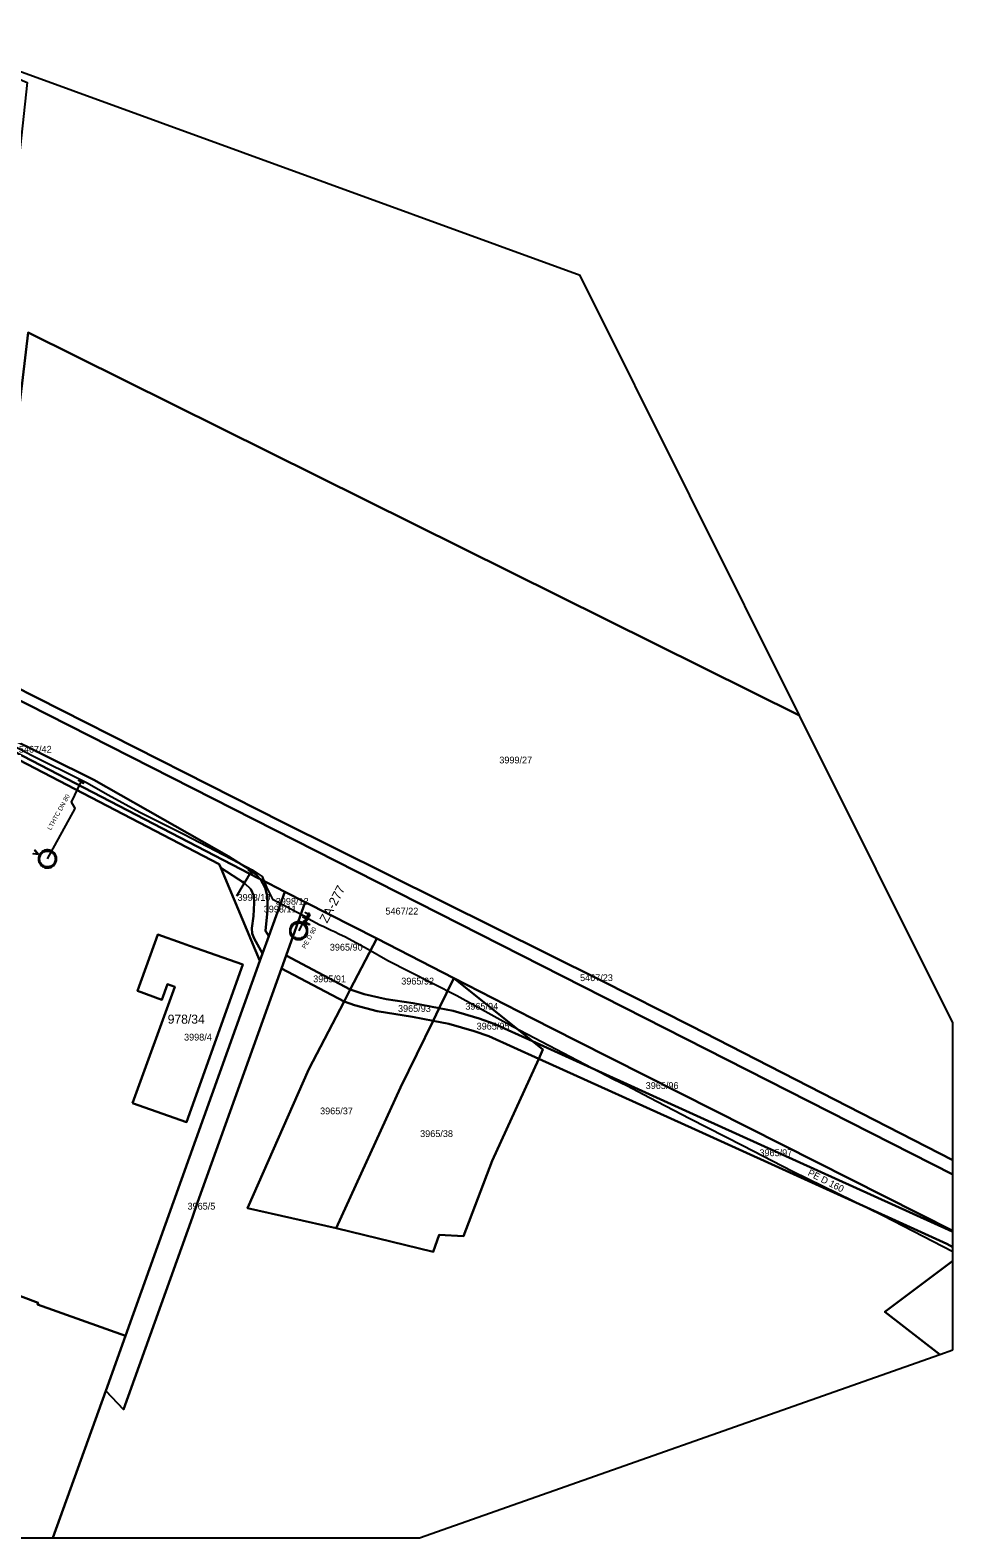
# Model space of a CAD drawing. Extents: x -570104 to -569328, y -1087857 to -1087418.
# Drawn here: x -569531.5 to -569327.7, y -1087857 to -1087524.1 of the extents above; entities that cross this region are included whole.
import ezdxf

# ---------------------------------------------------------------- set-up
doc = ezdxf.new("R2010")
doc.units = 0
for name, color, linetype in [('Adresní místo-text', 7, 'Continuous'), ('Armatura - popis', 7, 'Continuous'), ('Armatura vodovodní', 7, 'Continuous'), ('Default', 7, 'Continuous'), ('Lomový bod', 7, 'Continuous'), ('Parcela-polygon', 7, 'Continuous'), ('Parcela-text', 7, 'Continuous'), ('Přípojka vodovodní popis', 7, 'Continuous'), ('Vodovodní přípojka', 7, 'Continuous'), ('Vodovodní řad', 7, 'Continuous'), ('Vodovodní šachta', 7, 'Continuous'), ('Změna materiálu', 7, 'Continuous'), ('Řad vodovodní popis', 7, 'Continuous')]:
    doc.layers.add(name, color=color, linetype=linetype)

msp = doc.modelspace()

# ---------------------------------------------------------------- linework, layer by layer
at = {"layer": 'Armatura vodovodní'}
for points in [[(-569520.82, -1087689.73), (-569519.73, -1087690.35), (-569519.77, -1087690.41), (-569520.86, -1087689.79), (-569520.82, -1087689.73)], [(-569482.26, -1087710.27), (-569483.29, -1087709.56), (-569483.24, -1087709.49), (-569482.21, -1087710.2), (-569482.26, -1087710.27)], [(-569470.18, -1087720.56), (-569471.27, -1087719.95), (-569471.23, -1087719.89), (-569470.14, -1087720.49), (-569470.18, -1087720.56)], [(-569469.8, -1087719.13), (-569470.97, -1087721.34), (-569471.1, -1087721.27), (-569469.94, -1087719.06), (-569469.8, -1087719.13)]]:
    msp.add_lwpolyline(points, dxfattribs=at)
at = {"layer": 'Default'}
for points in [[(-569530.04, -1087705.98), (-569529.94, -1087705.99), (-569529.87, -1087706.01), (-569529.93, -1087705.95), (-569529.99, -1087705.88)], [(-569529.48, -1087706.22), (-569529.25, -1087705.78), (-569528.81, -1087705.47), (-569528.38, -1087705.16), (-569527.83, -1087705.13), (-569527.28, -1087705.11), (-569526.82, -1087705.34), (-569526.36, -1087705.57), (-569526.06, -1087706.01), (-569525.75, -1087706.46), (-569525.73, -1087707), (-569525.71, -1087707.54), (-569525.94, -1087708), (-569526.17, -1087708.45), (-569526.61, -1087708.76), (-569527.06, -1087709.06), (-569527.6, -1087709.08), (-569528.13, -1087709.11), (-569528.59, -1087708.88), (-569529.06, -1087708.64), (-569529.36, -1087708.19), (-569529.67, -1087707.74), (-569529.69, -1087707.21), (-569529.7, -1087706.67), (-569529.48, -1087706.22)], [(-569529.26, -1087706.33), (-569529.45, -1087706.72), (-569529.44, -1087707.19), (-569529.43, -1087707.66), (-569529.16, -1087708.06), (-569528.89, -1087708.45), (-569528.48, -1087708.66), (-569528.08, -1087708.86), (-569527.61, -1087708.84), (-569527.14, -1087708.82), (-569526.75, -1087708.55), (-569526.36, -1087708.29), (-569526.16, -1087707.89), (-569525.96, -1087707.48), (-569525.98, -1087707.01), (-569526, -1087706.54), (-569526.26, -1087706.15), (-569526.53, -1087705.76), (-569526.93, -1087705.56), (-569527.33, -1087705.36), (-569527.81, -1087705.38), (-569528.29, -1087705.4), (-569528.68, -1087705.67), (-569529.06, -1087705.94), (-569529.26, -1087706.33)], [(-569484.57, -1087712.21), (-569484.58, -1087712.21), (-569484.58, -1087712.2), (-569484.59, -1087712.19), (-569484.59, -1087712.18), (-569484.59, -1087712.17), (-569484.58, -1087712.16), (-569484.58, -1087712.15), (-569484.57, -1087712.15)], [(-569484.53, -1087712.15), (-569484.52, -1087712.15), (-569484.52, -1087712.16), (-569484.51, -1087712.17), (-569484.51, -1087712.18), (-569484.51, -1087712.19), (-569484.52, -1087712.2), (-569484.52, -1087712.21), (-569484.53, -1087712.21)], [(-569472.22, -1087720.97), (-569471.72, -1087720.97), (-569471.25, -1087721.22), (-569470.78, -1087721.48), (-569470.51, -1087721.95), (-569470.24, -1087722.43), (-569470.24, -1087722.95), (-569470.24, -1087723.46), (-569470.5, -1087723.93), (-569470.76, -1087724.4), (-569471.24, -1087724.66), (-569471.71, -1087724.93), (-569472.22, -1087724.93), (-569472.73, -1087724.93), (-569473.2, -1087724.66), (-569473.68, -1087724.4), (-569473.94, -1087723.93), (-569474.2, -1087723.46), (-569474.2, -1087722.95), (-569474.2, -1087722.43), (-569473.93, -1087721.95), (-569473.67, -1087721.48), (-569473.2, -1087721.22), (-569472.72, -1087720.97), (-569472.22, -1087720.97)], [(-569472.22, -1087721.21), (-569472.66, -1087721.21), (-569473.07, -1087721.44), (-569473.49, -1087721.66), (-569473.72, -1087722.08), (-569473.95, -1087722.5), (-569473.95, -1087722.95), (-569473.95, -1087723.4), (-569473.72, -1087723.81), (-569473.49, -1087724.22), (-569473.08, -1087724.45), (-569472.67, -1087724.68), (-569472.22, -1087724.68), (-569471.77, -1087724.68), (-569471.36, -1087724.45), (-569470.94, -1087724.22), (-569470.72, -1087723.81), (-569470.49, -1087723.4), (-569470.49, -1087722.95), (-569470.49, -1087722.5), (-569470.72, -1087722.08), (-569470.96, -1087721.66), (-569471.37, -1087721.44), (-569471.79, -1087721.21), (-569472.22, -1087721.21)]]:
    msp.add_open_spline(points, degree=3, dxfattribs=at)
at = {"layer": 'Lomový bod'}
for points in [[(-569484.6, -1087712.09), (-569484.6, -1087712.08), (-569484.5, -1087712.08), (-569484.5, -1087712.09), (-569484.53, -1087712.15)], [(-569484.57, -1087712.15), (-569484.6, -1087712.09)], [(-569484.53, -1087712.21), (-569484.5, -1087712.27), (-569484.5, -1087712.28), (-569484.6, -1087712.28), (-569484.6, -1087712.27), (-569484.57, -1087712.21)]]:
    msp.add_lwpolyline(points, dxfattribs=at)
at = {"layer": 'Parcela-polygon'}
for p, q in [((-569327.71, -1087743.27), (-569361.55, -1087675.44)), ((-569327.71, -1087773.61), (-569327.71, -1087743.27)), ((-569327.71, -1087776.81), (-569327.71, -1087773.61)), ((-569327.71, -1087789.25), (-569327.71, -1087776.81)), ((-569327.71, -1087789.45), (-569327.71, -1087789.25)), ((-569327.71, -1087792.83), (-569327.71, -1087789.45)), ((-569327.71, -1087795.88), (-569327.71, -1087792.83)), ((-569327.71, -1087815.54), (-569327.71, -1087795.88)), ((-569445.51, -1087857.02), (-569330.6, -1087816.56)), ((-569330.6, -1087816.56), (-569327.71, -1087815.54)), ((-569552.33, -1087857.02), (-569526.52, -1087857.02)), ((-569526.52, -1087857.02), (-569445.51, -1087857.02))]:
    msp.add_line(p, q, dxfattribs=at)
for points in [[(-569361.55, -1087675.44), (-569410.01, -1087578.31), (-569559, -1087524.1)], [(-569559, -1087524.1), (-569532.21, -1087535.63), (-569546.02, -1087663.53), (-569540.95, -1087665.98), (-569531.99, -1087590.85), (-569361.55, -1087675.44)], [(-569361.55, -1087675.44), (-569531.99, -1087590.85), (-569540.95, -1087665.98), (-569475.81, -1087698.97), (-569405.39, -1087733.98), (-569385.57, -1087743.95), (-569327.71, -1087773.61)], [(-569327.71, -1087773.61), (-569385.57, -1087743.95), (-569405.39, -1087733.98), (-569475.81, -1087698.97), (-569540.95, -1087665.98), (-569541.23, -1087668.35), (-569327.71, -1087776.81)], [(-569327.71, -1087776.81), (-569541.23, -1087668.35)], [(-569547.98, -1087674.52), (-569517.48, -1087689.67), (-569487.65, -1087706.59), (-569482.62, -1087709.76), (-569481.46, -1087710.69), (-569480.67, -1087711.59), (-569475.3, -1087714.34), (-569470.75, -1087716.66), (-569454.98, -1087724.71), (-569437.91, -1087733.43), (-569420.69, -1087742.27), (-569410.7, -1087747.32), (-569327.71, -1087789.25)], [(-569577.45, -1087857.02), (-569556.58, -1087797.77), (-569556.02, -1087796.19), (-569541.61, -1087801.32), (-569541.34, -1087800.75), (-569529.77, -1087805.11), (-569529.88, -1087805.5), (-569510.5, -1087812.41), (-569480.79, -1087729.63), (-569489.42, -1087709.06), (-569489.76, -1087708.24), (-569539.35, -1087682.53), (-569546.41, -1087703.53), (-569564.62, -1087755), (-569575.22, -1087784.93), (-569579.43, -1087783.46), (-569581.07, -1087788.14), (-569602.51, -1087849.39), (-569605.18, -1087857.02)], [(-569508.9, -1087761), (-569499.6, -1087735.35), (-569501.2, -1087734.77), (-569502.44, -1087738.2), (-569507.8, -1087736.26), (-569503.31, -1087723.78), (-569497.94, -1087725.68), (-569496.3, -1087726.26), (-569484.52, -1087730.43), (-569497.01, -1087765.21), (-569508.9, -1087761)], [(-569327.71, -1087792.83), (-569329.07, -1087792.09), (-569384.64, -1087766.88), (-569419.18, -1087751.25), (-569429.44, -1087773.79), (-569435.8, -1087790.42), (-569441.16, -1087790.1), (-569442.54, -1087793.88), (-569463.95, -1087788.64), (-569483.52, -1087784.23), (-569469.94, -1087753.56), (-569462.19, -1087738.61), (-569476.01, -1087731.32), (-569494.54, -1087782.95), (-569495.71, -1087786.22), (-569510.94, -1087828.67), (-569514.85, -1087824.53), (-569526.52, -1087857.02)], [(-569327.71, -1087789.25), (-569410.7, -1087747.32), (-569420.69, -1087742.27), (-569437.91, -1087733.43), (-569420.56, -1087747.36), (-569383.43, -1087764.17), (-569327.89, -1087789.36), (-569327.71, -1087789.45)], [(-569327.71, -1087789.45), (-569327.89, -1087789.36), (-569383.43, -1087764.17), (-569420.56, -1087747.36), (-569418.25, -1087749.21), (-569419.18, -1087751.25), (-569384.64, -1087766.88), (-569329.07, -1087792.09), (-569327.71, -1087792.83)], [(-569526.52, -1087857.02), (-569514.85, -1087824.53), (-569510.5, -1087812.41), (-569529.88, -1087805.5), (-569529.77, -1087805.11), (-569541.34, -1087800.75), (-569541.61, -1087801.32), (-569556.02, -1087796.19), (-569556.58, -1087797.77), (-569577.45, -1087857.02)], [(-569327.71, -1087795.88), (-569342.73, -1087807.12), (-569330.6, -1087816.56)], [(-569330.6, -1087816.56), (-569342.73, -1087807.12), (-569327.71, -1087795.88)]]:
    msp.add_lwpolyline(points, dxfattribs=at)
for points in [[(-569538.96, -1087681.38), (-569481.19, -1087711.33), (-569480.67, -1087711.59), (-569481.46, -1087710.69), (-569482.62, -1087709.76), (-569487.65, -1087706.59), (-569517.48, -1087689.67), (-569547.98, -1087674.52), (-569583.46, -1087656.2), (-569581.88, -1087657.43), (-569580.22, -1087659.19), (-569578.84, -1087661.42), (-569578.63, -1087662.1)], [(-569480.2, -1087727.99), (-569478.82, -1087724.15), (-569479.55, -1087722.98), (-569479.11, -1087718.52), (-569479.11, -1087715.5), (-569479.61, -1087713.5), (-569480.67, -1087711.59), (-569481.19, -1087711.33), (-569538.96, -1087681.38), (-569539.35, -1087682.53), (-569489.76, -1087708.24), (-569489.42, -1087709.06), (-569484.19, -1087712.45), (-569482.77, -1087713.8), (-569482.16, -1087715.26), (-569482.07, -1087716.83), (-569482.23, -1087719.78), (-569482.55, -1087722.4), (-569482.46, -1087723.59), (-569482.05, -1087724.68)], [(-569489.42, -1087709.06), (-569480.79, -1087729.63), (-569480.2, -1087727.99), (-569482.05, -1087724.68), (-569482.46, -1087723.59), (-569482.55, -1087722.4), (-569482.23, -1087719.78), (-569482.07, -1087716.83), (-569482.16, -1087715.26), (-569482.77, -1087713.8), (-569484.19, -1087712.45)], [(-569478.82, -1087724.15), (-569475.3, -1087714.34), (-569480.67, -1087711.59), (-569479.61, -1087713.5), (-569479.11, -1087715.5), (-569479.11, -1087718.52), (-569479.55, -1087722.98)], [(-569514.85, -1087824.53), (-569510.94, -1087828.67), (-569495.71, -1087786.22), (-569494.54, -1087782.95), (-569476.01, -1087731.32), (-569474.98, -1087728.45), (-569470.75, -1087716.66), (-569475.3, -1087714.34), (-569478.82, -1087724.15), (-569480.2, -1087727.99), (-569480.79, -1087729.63), (-569510.5, -1087812.41)], [(-569474.98, -1087728.45), (-569460.81, -1087735.95), (-569454.98, -1087724.71), (-569470.75, -1087716.66)], [(-569508.9, -1087761), (-569497.01, -1087765.21), (-569484.52, -1087730.43), (-569496.3, -1087726.26), (-569497.94, -1087725.68), (-569503.31, -1087723.78), (-569507.8, -1087736.26), (-569502.44, -1087738.2), (-569501.2, -1087734.77), (-569499.6, -1087735.35)], [(-569460.81, -1087735.95), (-569457.74, -1087736.99), (-569452.87, -1087738.05), (-569446.95, -1087738.96), (-569441.15, -1087740.04), (-569437.91, -1087733.43), (-569454.98, -1087724.71)], [(-569462.19, -1087738.61), (-569460.81, -1087735.95), (-569474.98, -1087728.45), (-569476.01, -1087731.32)], [(-569441.15, -1087740.04), (-569438.09, -1087740.68), (-569432.36, -1087742.36), (-569429.01, -1087743.51), (-569420.56, -1087747.36), (-569437.91, -1087733.43)], [(-569442.54, -1087742.86), (-569441.15, -1087740.04), (-569446.95, -1087738.96), (-569452.87, -1087738.05), (-569457.74, -1087736.99), (-569460.81, -1087735.95), (-569462.19, -1087738.61), (-569459.92, -1087739.43), (-569454.87, -1087740.7), (-569447.08, -1087741.94)], [(-569463.95, -1087788.64), (-569449.76, -1087757.58), (-569442.54, -1087742.86), (-569447.08, -1087741.94), (-569454.87, -1087740.7), (-569459.92, -1087739.43), (-569462.19, -1087738.61), (-569469.94, -1087753.56), (-569483.52, -1087784.23)], [(-569419.18, -1087751.25), (-569418.25, -1087749.21), (-569420.56, -1087747.36), (-569429.01, -1087743.51), (-569432.36, -1087742.36), (-569438.09, -1087740.68), (-569441.15, -1087740.04), (-569442.54, -1087742.86), (-569439.05, -1087743.5), (-569433.43, -1087745.13), (-569430.21, -1087746.25)], [(-569441.16, -1087790.1), (-569435.8, -1087790.42), (-569429.44, -1087773.79), (-569419.18, -1087751.25), (-569430.21, -1087746.25), (-569433.43, -1087745.13), (-569439.05, -1087743.5), (-569442.54, -1087742.86), (-569449.76, -1087757.58), (-569463.95, -1087788.64), (-569442.54, -1087793.88)]]:
    msp.add_lwpolyline(points, close=True, dxfattribs=at)
at = {"layer": 'Vodovodní přípojka'}
for points in [[(-569527.71, -1087707.11), (-569521.6, -1087696), (-569522.4, -1087694.54), (-569520.3, -1087690.07), (-569520.12, -1087689.7)], [(-569482.49, -1087709.5), (-569482.75, -1087709.88), (-569485.96, -1087715.35)], [(-569471.1, -1087720.67), (-569472.22, -1087722.95)]]:
    msp.add_lwpolyline(points, dxfattribs=at)
at = {"layer": 'Vodovodní řad'}
msp.add_lwpolyline([(-569535.61, -1087681.94), (-569530.97, -1087684.32), (-569520.12, -1087689.7), (-569519.07, -1087690.25), (-569514.34, -1087692.92), (-569507.29, -1087696.75), (-569497.57, -1087701.66), (-569483.62, -1087708.92), (-569482.49, -1087709.5), (-569480.25, -1087710.98), (-569479.3, -1087713.31), (-569477.99, -1087715.99), (-569471.04, -1087719.69), (-569470.68, -1087719.92), (-569470.11, -1087720.27), (-569467.56, -1087721.63), (-569466.68, -1087722.06), (-569465.79, -1087722.5), (-569465.07, -1087722.81), (-569464.34, -1087723.13), (-569463.19, -1087723.7), (-569462.03, -1087724.27), (-569456.9, -1087727.06), (-569452.54, -1087729.5), (-569447.76, -1087731.98), (-569437.31, -1087737.29), (-569424.9, -1087744.11), (-569413.8, -1087749.93), (-569402.65, -1087755.73), (-569399.71, -1087757.17), (-569394.7, -1087759.77), (-569385.81, -1087764.39), (-569374.14, -1087770.35), (-569363.14, -1087776.03), (-569343.13, -1087785.85), (-569327.71, -1087793.8)], dxfattribs=at)
at = {"layer": 'Vodovodní šachta'}
for points in [[(-569529.8, -1087706.12), (-569530.87, -1087706.01), (-569530.8, -1087705.89), (-569530.04, -1087705.98)], [(-569529.99, -1087705.88), (-569530.52, -1087705.31), (-569530.46, -1087705.19), (-569529.74, -1087705.99), (-569529.8, -1087706.12)]]:
    msp.add_lwpolyline(points, dxfattribs=at)
at = {"layer": 'Změna materiálu'}
msp.add_lwpolyline([(-569469.93, -1087719.48), (-569470.74, -1087719.02), (-569470.68, -1087718.91), (-569469.75, -1087719.44), (-569470.68, -1087721.07), (-569469.86, -1087721.53), (-569469.93, -1087721.64), (-569470.85, -1087721.12), (-569469.93, -1087719.48)], dxfattribs=at)

# ---------------------------------------------------------------- texts
at = {"layer": 'Adresní místo-text'}
msp.add_text('978/34', height=2, dxfattribs=at).set_placement((-569501.15, -1087743.49))
at = {"layer": 'Armatura - popis'}
msp.add_text('ZA-277', height=2, rotation=62.3147, dxfattribs=at).set_placement((-569465.94, -1087721.42))
at = {"layer": 'Parcela-text'}
for s, p in [('5467/42', (-569534.03, -1087683.64)), ('3999/27', (-569427.9, -1087686.02)), ('3998/10', (-569485.72, -1087716.36)), ('3998/12', (-569477.28, -1087717.22)), ('3998/11', (-569479.94, -1087718.93)), ('5467/22', (-569453.05, -1087719.38)), ('3965/90', (-569465.34, -1087727.35)), ('3965/91', (-569469.02, -1087734.34)), ('3965/92', (-569449.56, -1087734.84)), ('5467/23', (-569410.06, -1087734.08)), ('3965/93', (-569450.28, -1087740.88)), ('3965/94', (-569435.4, -1087740.4)), ('3965/95', (-569432.91, -1087744.79)), ('3998/4', (-569497.54, -1087747.21)), ('3965/96', (-569395.56, -1087757.9)), ('3965/37', (-569467.49, -1087763.5)), ('3965/38', (-569445.39, -1087768.52)), ('3965/97', (-569370.44, -1087772.74)), ('3965/5', (-569496.77, -1087784.54))]:
    msp.add_text(s, height=1.5, dxfattribs=at).set_placement(p)
at = {"layer": 'Přípojka vodovodní popis'}
for s, rotation, p in [('LTHTC DN 80', 61.194, (-569526.94, -1087700.85)), ('PE D 90', 60.9347, (-569470.73, -1087727.02))]:
    msp.add_text(s, height=1, rotation=rotation, dxfattribs=at).set_placement(p)
at = {"layer": 'Řad vodovodní popis'}
msp.add_text('PE D 160', height=1.5, rotation=333.1494, dxfattribs=at).set_placement((-569359.91, -1087776.9))

doc.saveas('drawing.dxf')
